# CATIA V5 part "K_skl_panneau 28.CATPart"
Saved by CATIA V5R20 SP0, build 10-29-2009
Part number: skl_panneau 28
Publications: "longueur axe pivot", "liaison 28/38", "liaison 24/28", "liaison 21/28", "liaison 28/29 sur 28", "Plan.00", "Droite.1", "Droite.2", "Droite.3", "Droite.4", "Droite.5", "Droite.6", "Droite.7"
Bounding box of the stored display mesh (mm): x -150 to 0, y 150 to 340, z -55 to 445
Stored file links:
  G:\Khaled_CFAO_2011\SIL\SIL_GR2\mdardier\Khaled\CAD_ThinkMOTION\K_skl_panneau 28.CATPart
  G:\Khaled_CFAO_2011\SIL\SIL_GR2\mdardier\Khaled\CAD_ThinkMOTION\K_skl_ass_tandem.CATProduct
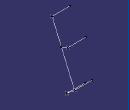
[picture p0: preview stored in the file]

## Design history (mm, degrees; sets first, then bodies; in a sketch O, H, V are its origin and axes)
External parameters (linked from other documents)
  `External.longueur axe pivot` = 150 mm
Set1
  Point1 "liaison 28/38": linked copy from another document
  Point2 "liaison 24/28": linked copy from another document
  Point3 "liaison 21/28": linked copy from another document
  Point4 "liaison 28/29 sur 28": linked copy from another document
  Plane1 "Plan.00": linked copy from another document
Set2
  Line1: type PtPt, FirstPoint Point1, SecondPoint Point2
  Line2: type PtPt, FirstPoint Point2, SecondPoint Point3
  Line3: type Angle, LineFirstUpto Line2, RefPoint Point4, Start 0, End 0, Angle 90
  Line4: type Normal, RefPoint Point1, RefSkin Plane1, Start 0, End 150 {= `External.longueur axe pivot`}
  Line5: type Normal, RefPoint Point2, RefSkin Plane1, Start 0, End 150 {= `External.longueur axe pivot`}
  Line6: type Normal, RefPoint Point4, RefSkin Plane1, Start 0, End 150 {= `External.longueur axe pivot`}
  Line7: type Normal, RefPoint Point3, RefSkin Plane1, Start 0, End 150 {= `External.longueur axe pivot`}
Body1 (main body)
